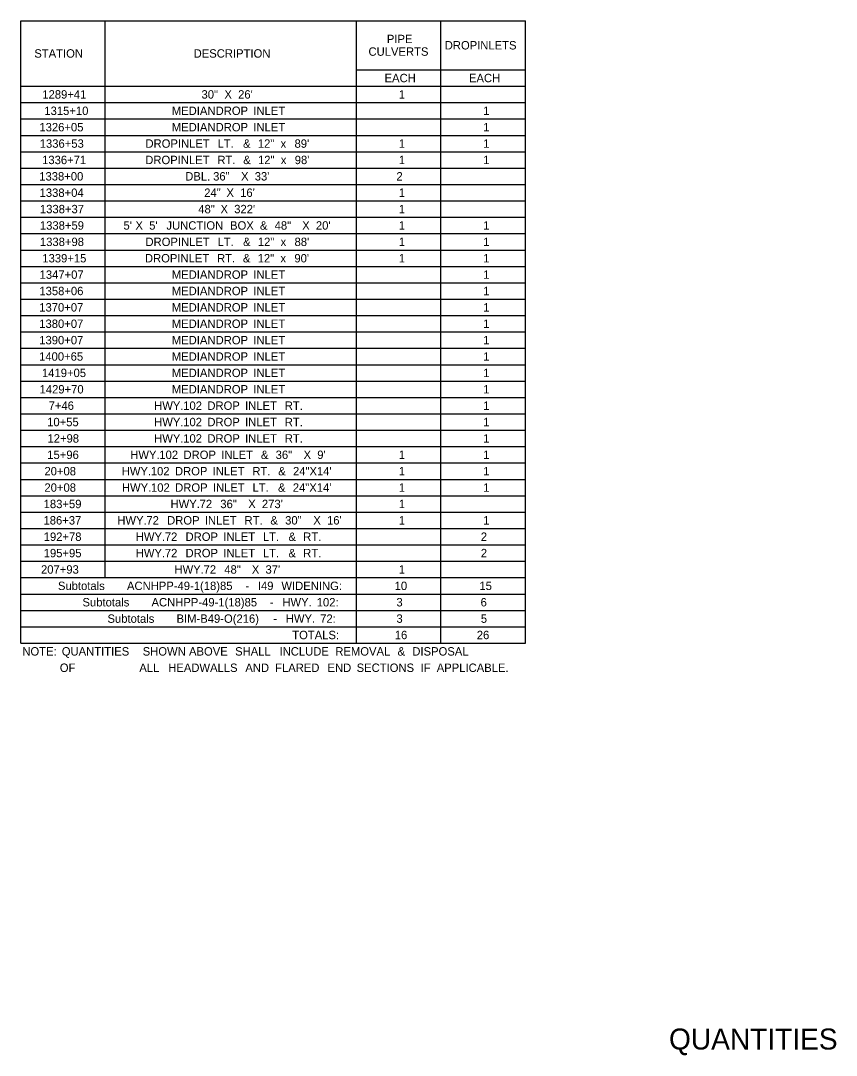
# Model space of a CAD drawing. Extents: x 1226657 to 1228145, y 151309 to 152305.
# Drawn here: x 1227645 to 1228130, y 151309 to 151925 of the extents above; entities that cross this region are included whole.
import ezdxf

# ---------------------------------------------------------------- set-up
doc = ezdxf.new("R2010")
doc.units = 0
doc.layers.add('R_Border Notes', color=7, linetype='Continuous')
doc.layers.add('R_Dimension', color=7, linetype='Continuous')

msp = doc.modelspace()

# ---------------------------------------------------------------- linework, layer by layer
at = {"layer": 'R_Dimension'}
for p, q in [((1227645.01, 151925.19), (1227945.31, 151925.19)), ((1227645.01, 151554.69), (1227645.01, 151925.19)), ((1227695.23, 151593.69), (1227695.23, 151925.19)), ((1227844.89, 151554.69), (1227844.89, 151925.19)), ((1227895.1, 151554.69), (1227895.1, 151925.19)), ((1227945.31, 151554.69), (1227945.31, 151925.19)), ((1227844.89, 151895.94), (1227945.31, 151895.94)), ((1227645.01, 151886.19), (1227945.31, 151886.19)), ((1227645.01, 151876.44), (1227945.31, 151876.44)), ((1227645.01, 151866.69), (1227945.31, 151866.69)), ((1227645.01, 151856.94), (1227945.31, 151856.94)), ((1227645.01, 151847.19), (1227945.31, 151847.19)), ((1227645.01, 151837.44), (1227945.31, 151837.44)), ((1227645.01, 151827.69), (1227945.31, 151827.69)), ((1227645.01, 151817.94), (1227945.31, 151817.94)), ((1227645.01, 151808.19), (1227945.31, 151808.19)), ((1227645.01, 151798.44), (1227945.31, 151798.44)), ((1227645.01, 151788.69), (1227945.31, 151788.69)), ((1227645.01, 151778.94), (1227945.31, 151778.94)), ((1227645.01, 151769.19), (1227945.31, 151769.19)), ((1227645.01, 151759.44), (1227945.31, 151759.44)), ((1227645.01, 151749.69), (1227945.31, 151749.69)), ((1227645.01, 151739.94), (1227945.31, 151739.94)), ((1227645.01, 151730.19), (1227945.31, 151730.19)), ((1227645.01, 151720.44), (1227945.31, 151720.44)), ((1227645.01, 151710.69), (1227945.31, 151710.69)), ((1227645.01, 151700.94), (1227945.31, 151700.94)), ((1227645.01, 151691.19), (1227945.31, 151691.19)), ((1227645.01, 151681.44), (1227945.31, 151681.44)), ((1227645.01, 151671.69), (1227945.31, 151671.69)), ((1227645.01, 151661.94), (1227945.31, 151661.94)), ((1227645.01, 151652.19), (1227945.31, 151652.19)), ((1227645.01, 151642.44), (1227945.31, 151642.44)), ((1227645.01, 151632.69), (1227945.31, 151632.69)), ((1227645.01, 151622.94), (1227945.31, 151622.94)), ((1227645.01, 151613.19), (1227945.31, 151613.19)), ((1227645.01, 151603.44), (1227945.31, 151603.44)), ((1227645.01, 151593.69), (1227945.31, 151593.69)), ((1227645.01, 151583.94), (1227945.31, 151583.94)), ((1227645.01, 151574.19), (1227945.31, 151574.19)), ((1227645.01, 151564.44), (1227945.31, 151564.44)), ((1227645.01, 151554.69), (1227945.31, 151554.69))]:
    msp.add_line(p, q, dxfattribs=at)

# ---------------------------------------------------------------- texts
at = {"layer": 'R_Border Notes'}
msp.add_text('QUANTITIES', height=12.5, dxfattribs=at).set_placement((1228030.78, 151312.82))
at = {"layer": 'R_Dimension'}
for s, p in [('PIPE', (1227862.91, 151911.81)), ('DROP', (1227897.33, 151908.06)), (' INLETS', (1227914.77, 151908.06)), ('STATION', (1227653.11, 151903.19)), ('DESCRIPTION', (1227747.91, 151903.19)), ('CULVERTS', (1227851.96, 151904.31)), ('EACH', (1227861.53, 151888.56)), ('EACH', (1227911.74, 151888.56)), ('1289+41', (1227657.88, 151878.81)), ('30"', (1227752.6, 151878.81)), (' X', (1227764.37, 151878.81)), (" 26'", (1227772.52, 151878.81)), ('1', (1227869.99, 151878.81)), ('1315+10', (1227659.08, 151869.06)), ('MEDIAN', (1227734.92, 151869.06)), (' DROP', (1227759.13, 151869.06)), (' INLET', (1227781.57, 151869.06)), ('1', (1227920.21, 151869.06)), ('1326+05', (1227656.14, 151859.31)), ('MEDIAN', (1227734.92, 151859.31)), (' DROP', (1227759.13, 151859.31)), (' INLET', (1227781.57, 151859.31)), ('1', (1227920.21, 151859.31)), ('1336+53', (1227656.34, 151849.56)), ('DROP', (1227719.25, 151849.56)), (' INLET', (1227736.69, 151849.56)), (' LT.', (1227760.31, 151849.56)), (' &', (1227775.47, 151849.56)), (' 12"', (1227784.25, 151849.56)), (' x', (1227797.79, 151849.56)), (" 89'", (1227806.1, 151849.56)), ('1', (1227869.99, 151849.56)), ('1', (1227920.21, 151849.56)), ('1336+71', (1227657.76, 151839.81)), ('DROP', (1227719.13, 151839.81)), (' INLET', (1227736.57, 151839.81)), (' RT.', (1227760.2, 151839.81)), (' &', (1227775.59, 151839.81)), (' 12"', (1227784.37, 151839.81)), (" 98'", (1227806.22, 151839.81)), ('1', (1227869.99, 151839.81)), ('1', (1227920.21, 151839.81)), (' x', (1227797.91, 151839.81)), ('1338+00', (1227656.05, 151830.06)), ('DBL.', (1227742.93, 151830.06)), (' 36"', (1227757.66, 151830.06)), (' X', (1227774.27, 151830.06)), (" 33'", (1227782.42, 151830.06)), ('2', (1227868.58, 151830.06)), ('1338+04', (1227656.26, 151820.31)), ('24"', (1227754.21, 151820.31)), (' X', (1227765.59, 151820.31)), (" 16'", (1227773.74, 151820.31)), ('1', (1227869.99, 151820.31)), ('1338+37', (1227656.46, 151810.56)), ('48"', (1227750.67, 151810.56)), (' X', (1227762.05, 151810.56)), (" 322'", (1227770.2, 151810.56)), ('1', (1227869.99, 151810.56)), ('1338+59', (1227656.44, 151800.81)), ("5'", (1227706.16, 151800.81)), (' X', (1227711.44, 151800.81)), (" 5'", (1227719.59, 151800.81)), (' JUNCTION', (1227729.86, 151800.81)), (' BOX', (1227767.73, 151800.81)), (' &', (1227785.49, 151800.81)), (' 48"', (1227794.27, 151800.81)), (' X', (1227810.65, 151800.81)), (" 20'", (1227818.8, 151800.81)), ('1', (1227869.99, 151800.81)), ('1', (1227920.21, 151800.81)), ('1338+98', (1227656.46, 151791.06)), ('DROP', (1227719.25, 151791.06)), (' INLET', (1227736.69, 151791.06)), (' LT.', (1227760.31, 151791.06)), (' &', (1227775.47, 151791.06)), (' 12"', (1227784.25, 151791.06)), (" 88'", (1227806.1, 151791.06)), ('1', (1227869.99, 151791.06)), ('1', (1227920.21, 151791.06)), (' x', (1227797.79, 151791.06)), ('1339+15', (1227657.88, 151781.31)), ('DROP', (1227718.94, 151781.31)), (' INLET', (1227736.38, 151781.31)), (' RT.', (1227760, 151781.31)), (' &', (1227775.39, 151781.31)), (' 12"', (1227784.17, 151781.31)), (' x', (1227797.71, 151781.31)), (" 90'", (1227806.02, 151781.31)), ('1', (1227869.99, 151781.31)), ('1', (1227920.21, 151781.31)), ('1347+07', (1227656.26, 151771.56)), ('MEDIAN', (1227734.92, 151771.56)), (' DROP', (1227759.13, 151771.56)), (' INLET', (1227781.57, 151771.56)), ('1', (1227920.21, 151771.56)), ('1358+06', (1227656.12, 151761.81)), ('MEDIAN', (1227734.92, 151761.81)), (' DROP', (1227759.13, 151761.81)), (' INLET', (1227781.57, 151761.81)), ('1', (1227920.21, 151761.81)), ('1370+07', (1227656.06, 151752.06)), ('MEDIAN', (1227734.92, 151752.06)), (' DROP', (1227759.13, 151752.06)), (' INLET', (1227781.57, 151752.06)), ('1', (1227920.21, 151752.06)), ('1380+07', (1227656.06, 151742.31)), ('MEDIAN', (1227734.92, 151742.31)), (' DROP', (1227759.13, 151742.31)), (' INLET', (1227781.57, 151742.31)), ('1', (1227920.21, 151742.31)), ('1390+07', (1227656.06, 151732.56)), ('MEDIAN', (1227734.92, 151732.56)), (' DROP', (1227759.13, 151732.56)), (' INLET', (1227781.57, 151732.56)), ('1', (1227920.21, 151732.56)), ('1400+65', (1227655.95, 151722.81)), ('MEDIAN', (1227734.92, 151722.81)), (' DROP', (1227759.13, 151722.81)), (' INLET', (1227781.57, 151722.81)), ('1', (1227920.21, 151722.81)), ('1419+05', (1227657.68, 151713.06)), ('MEDIAN', (1227734.92, 151713.06)), (' DROP', (1227759.13, 151713.06)), (' INLET', (1227781.57, 151713.06)), ('1', (1227920.21, 151713.06)), ('1429+70', (1227656.24, 151703.31)), ('MEDIAN', (1227734.92, 151703.31)), (' DROP', (1227759.13, 151703.31)), (' INLET', (1227781.57, 151703.31)), ('1', (1227920.21, 151703.31)), ('7+46', (1227661.64, 151693.56)), ('HWY.', (1227724.43, 151693.56)), (' 102', (1227739.86, 151693.56)), (' DROP', (1227754.23, 151693.56)), (' INLET', (1227776.67, 151693.56)), (' RT.', (1227800.29, 151693.56)), ('1', (1227920.21, 151693.56)), ('10+55', (1227660.75, 151683.81)), ('HWY.', (1227724.43, 151683.81)), (' 102', (1227739.86, 151683.81)), (' DROP', (1227754.23, 151683.81)), (' INLET', (1227776.67, 151683.81)), (' RT.', (1227800.29, 151683.81)), ('1', (1227920.21, 151683.81)), ('12+98', (1227660.95, 151674.06)), ('HWY.', (1227724.43, 151674.06)), (' 102', (1227739.86, 151674.06)), (' DROP', (1227754.23, 151674.06)), (' INLET', (1227776.67, 151674.06)), (' RT.', (1227800.29, 151674.06)), ('1', (1227920.21, 151674.06)), ('15+96', (1227660.81, 151664.31)), ('HWY.', (1227710.21, 151664.31)), (' 102', (1227725.65, 151664.31)), (' DROP', (1227740.02, 151664.31)), (' INLET', (1227762.46, 151664.31)), (' &', (1227786.08, 151664.31)), (' 36"', (1227794.86, 151664.31)), (' X', (1227811.47, 151664.31)), (" 9'", (1227819.62, 151664.31)), ('1', (1227869.99, 151664.31)), ('1', (1227920.21, 151664.31)), ('20+08', (1227659.14, 151654.56)), ('HWY.', (1227705.14, 151654.56)), (' 102', (1227720.57, 151654.56)), (' DROP', (1227734.94, 151654.56)), (' INLET', (1227757.38, 151654.56)), (' RT.', (1227781, 151654.56)), (' &', (1227796.4, 151654.56)), (' 24"X14\'', (1227805.18, 151654.56)), ('1', (1227869.99, 151654.56)), ('1', (1227920.21, 151654.56)), ('20+08', (1227659.14, 151644.81)), ('HWY.', (1227705.25, 151644.81)), (' 102', (1227720.69, 151644.81)), (' DROP', (1227735.06, 151644.81)), (' INLET', (1227757.5, 151644.81)), (' LT.', (1227781.12, 151644.81)), (' &', (1227796.28, 151644.81)), (' 24"X14\'', (1227805.06, 151644.81)), ('1', (1227869.99, 151644.81)), ('1', (1227920.21, 151644.81)), ('183+59', (1227658.68, 151635.06)), ('HWY.', (1227734.17, 151635.06)), (' 72', (1227749.6, 151635.06)), (' 36"', (1227761.93, 151635.06)), (' X', (1227778.54, 151635.06)), (" 273'", (1227786.69, 151635.06)), ('1', (1227869.99, 151635.06)), ('186+37', (1227658.58, 151625.31)), ('HWY.', (1227702.52, 151625.31)), (' 72', (1227717.95, 151625.31)), (' DROP', (1227730.27, 151625.31)), (' INLET', (1227752.71, 151625.31)), (' RT.', (1227776.34, 151625.31)), (' &', (1227791.73, 151625.31)), (' 30"', (1227800.51, 151625.31)), (' X', (1227817.28, 151625.31)), (" 16'", (1227825.43, 151625.31)), ('1', (1227869.99, 151625.31)), ('1', (1227920.21, 151625.31)), ('192+78', (1227658.7, 151615.56)), ('HWY.', (1227713.48, 151615.56)), (' 72', (1227728.92, 151615.56)), (' DROP', (1227741.24, 151615.56)), (' INLET', (1227763.68, 151615.56)), (' LT.', (1227787.3, 151615.56)), (' &', (1227802.46, 151615.56)), (' RT.', (1227811.24, 151615.56)), ('2', (1227918.79, 151615.56)), ('195+95', (1227658.7, 151605.81)), ('HWY.', (1227713.48, 151605.81)), (' 72', (1227728.92, 151605.81)), (' DROP', (1227741.24, 151605.81)), (' INLET', (1227763.68, 151605.81)), (' LT.', (1227787.3, 151605.81)), (' &', (1227802.46, 151605.81)), (' RT.', (1227811.24, 151605.81)), ('2', (1227918.79, 151605.81)), ('207+93', (1227657.09, 151596.06)), ('HWY.', (1227736.53, 151596.06)), (' 72', (1227751.97, 151596.06)), (' 48"', (1227764.29, 151596.06)), (' X', (1227780.67, 151596.06)), (" 37'", (1227788.82, 151596.06)), ('1', (1227869.99, 151596.06)), ('Subtotals', (1227667.18, 151586.31)), (' ACNHPP-49-1(18)85', (1227706.39, 151586.31)), (' -', (1227776.82, 151586.31)), (' I49', (1227784.26, 151586.31)), (' WIDENING:', (1227798.28, 151586.31)), ('10', (1227867.53, 151586.31)), ('15', (1227917.96, 151586.31)), ('Subtotals', (1227681.78, 151576.56)), (' ACNHPP-49-1(18)85', (1227721, 151576.56)), (' HWY.', (1227798.87, 151576.56)), (' 102:', (1227819.3, 151576.56)), ('3', (1227868.58, 151576.56)), ('6', (1227918.65, 151576.56)), (' -', (1227791.43, 151576.56)), ('Subtotals', (1227696.66, 151566.81)), (' BIM-B49-O(216)', (1227735.88, 151566.81)), (' -', (1227793.48, 151566.81)), (' HWY.', (1227800.92, 151566.81)), (' 72:', (1227821.35, 151566.81)), ('3', (1227868.58, 151566.81)), ('5', (1227918.79, 151566.81)), ('TOTALS:', (1227806.59, 151557.06)), ('16', (1227867.61, 151557.06)), ('26', (1227916.41, 151557.06)), ('NOTE:', (1227645.99, 151547.31)), ('  QUANTITIES', (1227665.75, 151547.31)), (' SHOWN', (1227715.75, 151547.31)), (' ABOVE', (1227743.31, 151547.31)), (' SHALL', (1227770.75, 151547.31)), (' INCLUDE', (1227797.17, 151547.31)), (' REMOVAL', (1227830.36, 151547.31)), (' &', (1227867.41, 151547.31)), (' DISPOSAL', (1227876.19, 151547.31)), ('            OF', (1227645.99, 151537.56)), (' ALL', (1227713.74, 151537.56)), (' HEADWALLS', (1227730.95, 151537.56)), (' AND', (1227776.82, 151537.56)), (' FLARED', (1227794.53, 151537.56)), (' END', (1227825.71, 151537.56)), (' SECTIONS', (1227843.04, 151537.56)), (' IF', (1227881.19, 151537.56)), (' APPLICABLE.', (1227890.71, 151537.56))]:
    msp.add_text(s, height=5, dxfattribs=at).set_placement(p)

doc.saveas('drawing.dxf')
